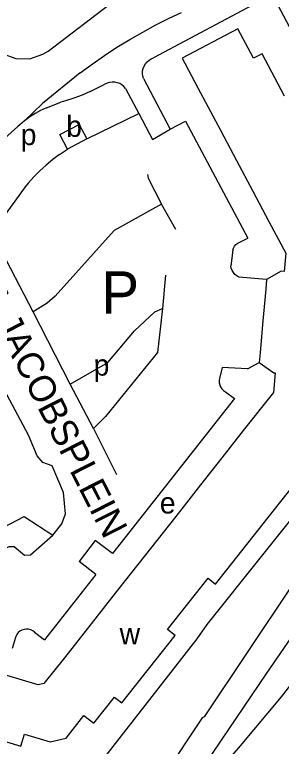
# Model space of a CAD drawing. Extents: x 159902 to 161769, y 383692 to 384875.
# Drawn here: x 160800.1 to 160850.4, y 383765 to 383903 of the extents above; entities that cross this region are included whole.
import ezdxf

# ---------------------------------------------------------------- set-up
doc = ezdxf.new("R2010")
doc.units = 0
for name, color, linetype in [('BLT_Basislijn', 7, 'Continuous'), ('BLT_Bebouwing', 7, 'Continuous'), ('BLT_Centroide', 7, 'Continuous'), ('BLT_Straatnaam', 7, 'Continuous'), ('BLT_Tekst_parkeren', 7, 'Continuous')]:
    doc.layers.add(name, color=color, linetype=linetype)

msp = doc.modelspace()

# ---------------------------------------------------------------- linework, layer by layer
at = {"layer": 'BLT_Basislijn'}
for p, q in [((160824.41, 383890.97), (160829.44, 383881.41)), ((160814.31, 383888.5), (160817.13, 383889.91)), ((160821, 383889.09), (160823.49, 383884.35)), ((160806.08, 383885.45), (160808.78, 383886.5)), ((160813.69, 383879.57), (160823.49, 383884.35)), ((160823.49, 383884.35), (160826.06, 383879.45)), ((160791.51, 383873.69), (160800.68, 383881.92)), ((160829.44, 383881.41), (160832.33, 383882.95)), ((160832.33, 383882.95), (160844.06, 383860.89)), ((160826.06, 383879.45), (160829.44, 383881.41)), ((160808.55, 383876.63), (160810.07, 383877.66)), ((160802.09, 383870.52), (160795.78, 383861.92)), ((160830.46, 383862.5), (160827.77, 383867.29)), ((160803.61, 383847), (160795.78, 383861.92)), ((160842.19, 383859.94), (160844.06, 383860.89)), ((160841.21, 383858.58), (160840.86, 383855.64)), ((160828.54, 383853.87), (160827.99, 383847.63)), ((160847.6, 383853.1), (160842.39, 383853.53)), ((160810.55, 383833.36), (160803.61, 383847)), ((160843.98, 383836.2), (160846.22, 383837.43)), ((160814.98, 383824.97), (160810.55, 383833.36)), ((160839.86, 383831.9), (160841.57, 383830.61)), ((160841.57, 383830.61), (160818.53, 383801.38)), ((160814.98, 383824.97), (160819.29, 383816.32)), ((160815.26, 383803.86), (160812.23, 383799.88)), ((160818.53, 383801.38), (160815.26, 383803.86)), ((160815.43, 383797.45), (160812.23, 383799.88)), ((160815.43, 383797.45), (160805.72, 383785.12)), ((160803.85, 383786.58), (160805.72, 383785.12)), ((160800.24, 383785.55), (160799.64, 383783.47)), ((160847.56, 383778.83), (160833.1, 383757.45))]:
    msp.add_line(p, q, dxfattribs=at)
for points in [[(160789.94, 383933.21), (160788.45, 383936.02), (160783.16, 383933.13), (160782.49, 383932.48), (160794.23, 383900.62), (160795.68, 383898.07), (160797.42, 383896), (160797.84, 383895.65), (160800.29, 383894.78), (160802.93, 383894.69), (160805.42, 383895.54), (160806.44, 383896.13), (160818.93, 383905.69), (160830.31, 383913.34), (160841.85, 383920.77), (160849.53, 383926.4), (160850.93, 383927.2)], [(160809.3, 383753.02), (160834.49, 383785.31), (160836.4, 383788.02), (160867.15, 383826.48), (160870.9, 383862.33), (160862.47, 383878.6), (160857.32, 383890.56), (160848.7, 383906.79)], [(160848.7, 383906.79), (160846.85, 383905.9), (160826.29, 383894.85)], [(160812.43, 383892.03), (160814.7, 383893.7), (160817.02, 383895.31), (160819.39, 383896.86), (160821.8, 383898.33), (160824.25, 383899.74), (160826.74, 383901.08), (160829.26, 383902.34), (160831.58, 383903.43)], [(160871.92, 383895.58), (160883.99, 383847.84), (160884.47, 383842.76), (160884.28, 383837.65), (160882.39, 383831.02), (160879.11, 383825.85), (160872.89, 383819), (160852.33, 383795.26), (160835.86, 383770.62), (160835.44, 383770.4), (160832.17, 383765.5), (160824.93, 383754.38), (160824.47, 383753.32), (160822.38, 383750.08), (160819.17, 383745.43)], [(160824.41, 383890.97), (160824.27, 383891.43), (160824.21, 383891.91), (160824.23, 383892.4), (160824.33, 383892.87), (160824.51, 383893.32), (160824.76, 383893.74), (160825.07, 383894.11), (160825.44, 383894.42), (160825.85, 383894.67), (160826.29, 383894.85)], [(160812.43, 383892.03), (160805.36, 383886.28), (160801.96, 383883.02)], [(160821, 383889.09), (160820.69, 383889.46), (160820.32, 383889.77), (160819.9, 383890.02), (160819.45, 383890.19), (160818.98, 383890.29), (160818.49, 383890.31), (160818.01, 383890.25), (160817.54, 383890.11), (160817.13, 383889.91)], [(160814.31, 383888.5), (160812.8, 383887.85), (160811.27, 383887.27), (160809.7, 383886.76), (160808.78, 383886.5)], [(160806.08, 383885.45), (160804.99, 383884.94), (160803.94, 383884.37), (160802.93, 383883.73), (160801.96, 383883.02)], [(160801.96, 383883.02), (160801.04, 383882.25), (160800.68, 383881.92)], [(160808.55, 383876.63), (160807.27, 383875.67), (160806.04, 383874.64), (160804.86, 383873.56), (160803.73, 383872.42), (160802.67, 383871.22), (160802.09, 383870.52)], [(160825.15, 383872.86), (160825.28, 383872.21), (160827.77, 383867.29)], [(160827.77, 383867.29), (160818.87, 383862.3), (160807.72, 383849.93), (160806.22, 383848.61), (160803.61, 383847)], [(160802.69, 383823.74), (160783.95, 383858.7), (160783.48, 383862.68), (160781.24, 383865.39), (160779.27, 383866.03), (160776.94, 383866.03), (160774.98, 383865.25), (160730.57, 383841.92), (160729.44, 383842.02), (160727.88, 383842.45)], [(160841.21, 383858.58), (160841.34, 383858.97), (160841.54, 383859.33), (160841.81, 383859.65), (160842.19, 383859.94)], [(160842.39, 383853.53), (160841.99, 383853.75), (160841.63, 383854.04), (160841.34, 383854.39), (160841.1, 383854.79), (160840.94, 383855.22), (160840.86, 383855.64)], [(160810.55, 383833.36), (160817.69, 383837.39), (160822.71, 383843.37), (160826.5, 383847), (160827.99, 383847.63)], [(160827.99, 383847.63), (160827.06, 383839.33), (160817.22, 383827.25), (160814.98, 383824.97)], [(160843.98, 383836.2), (160839.22, 383836.48), (160838.75, 383834.42)], [(160838.75, 383834.42), (160838.67, 383834.01), (160838.68, 383833.6), (160838.76, 383833.19), (160838.93, 383832.8), (160839.16, 383832.46), (160839.45, 383832.16), (160839.86, 383831.9)], [(160807.28, 383804.85), (160808.96, 383806.97), (160809.68, 383808.87), (160809.33, 383812.91), (160807.15, 383817.9), (160805.4, 383818.54), (160804.35, 383819.82), (160802.69, 383823.74)], [(160877.05, 383815.24), (160871.92, 383810.01), (160859.32, 383795.17), (160856.62, 383791.99), (160847.56, 383778.83)], [(160789.48, 383797.77), (160787.69, 383800.97), (160801.9, 383808.38), (160807.28, 383804.85)], [(160789.48, 383797.77), (160799.09, 383802.69), (160799.98, 383802.7), (160801.96, 383801.09), (160803.08, 383801.17), (160807.28, 383804.85)], [(160803.85, 383786.58), (160803.51, 383786.83), (160803.12, 383787.01), (160802.71, 383787.11), (160802.29, 383787.13), (160801.87, 383787.08), (160801.47, 383786.95), (160801.1, 383786.74), (160800.78, 383786.47), (160800.51, 383786.14), (160800.31, 383785.77), (160800.24, 383785.55)], [(160854.56, 383779.77), (160850.36, 383774.35), (160842.62, 383765.11), (160835.53, 383756.89)]]:
    msp.add_lwpolyline(points, dxfattribs=at)
at = {"layer": 'BLT_Bebouwing'}
for p, q in [((160831.7, 383894.79), (160834.65, 383889.23)), ((160834.65, 383889.23), (160838.89, 383881.24)), ((160810.07, 383877.66), (160808.62, 383880.39)), ((160838.89, 383881.24), (160841.94, 383875.5)), ((160813.69, 383879.57), (160810.07, 383877.66)), ((160841.94, 383875.5), (160844.99, 383869.76)), ((160844.99, 383869.76), (160848.04, 383864.02)), ((160847.6, 383853.1), (160847.44, 383851.24)), ((160847.44, 383851.24), (160846.91, 383845.27)), ((160846.91, 383845.27), (160846.38, 383839.29)), ((160846.38, 383839.29), (160846.22, 383837.43)), ((160843.21, 383824.58), (160839.19, 383819.47)), ((160839.19, 383819.47), (160835.17, 383814.36)), ((160850.06, 383810.92), (160854.08, 383816.03)), ((160835.17, 383814.36), (160831.15, 383809.26)), ((160846.04, 383805.82), (160850.06, 383810.92)), ((160831.15, 383809.26), (160827.13, 383804.15)), ((160842.02, 383800.71), (160846.04, 383805.82)), ((160827.13, 383804.15), (160823.32, 383799.31)), ((160823.32, 383799.31), (160819.52, 383794.47)), ((160832.75, 383791.89), (160836.56, 383796.73)), ((160819.52, 383794.47), (160814.51, 383788.11)), ((160828.94, 383787.05), (160832.75, 383791.89)), ((160814.51, 383788.11), (160809.51, 383781.74)), ((160809.51, 383781.74), (160805.61, 383776.86))]:
    msp.add_line(p, q, dxfattribs=at)
for points in [[(160845.16, 383894.81), (160842.21, 383900.37), (160831.7, 383894.79)], [(160850.99, 383887.66), (160846.74, 383895.65), (160845.16, 383894.81)], [(160808.62, 383880.39), (160812.24, 383882.31), (160813.69, 383879.57)], [(160848.04, 383864.02), (160851.22, 383858.02), (160850.92, 383854.6), (160850.34, 383854.65), (160847.6, 383853.1)], [(160846.22, 383837.43), (160848.98, 383835.49), (160849.21, 383835.47), (160848.88, 383831.79), (160843.21, 383824.58)], [(160836.56, 383796.73), (160838, 383795.6), (160842.02, 383800.71)], [(160825.34, 383779.58), (160830.35, 383785.95), (160828.94, 383787.05)], [(160805.61, 383776.86), (160804.54, 383776.61), (160798.62, 383778.39)], [(160818.93, 383774.33), (160820.33, 383773.22), (160825.34, 383779.58)], [(160813.16, 383770.87), (160815.05, 383769.39), (160818.93, 383774.33)], [(160795.16, 383766.9), (160801.23, 383765.07), (160801.92, 383767.35), (160806.79, 383765.88), (160809.79, 383766.58), (160813.16, 383770.87)]]:
    msp.add_lwpolyline(points, dxfattribs=at)

# ---------------------------------------------------------------- texts
at = {"layer": 'BLT_Centroide'}
for s, p in [('b', (160809.82, 383879.97)), ('p', (160801.23, 383878.41)), ('p', (160814.98, 383834.94)), ('e', (160827.47, 383808.94)), ('w', (160819.89, 383784.25))]:
    msp.add_text(s, height=4, dxfattribs=at).set_placement(p)
at = {"layer": 'BLT_Straatnaam'}
msp.add_text('ALETTA JACOBSPLEIN', height=5, rotation=296.9685, dxfattribs=at).set_placement((160783.91, 383869.11))
at = {"layer": 'BLT_Tekst_parkeren'}
msp.add_text('P', height=8, dxfattribs=at).set_placement((160816.43, 383846.61))

doc.saveas('drawing.dxf')
